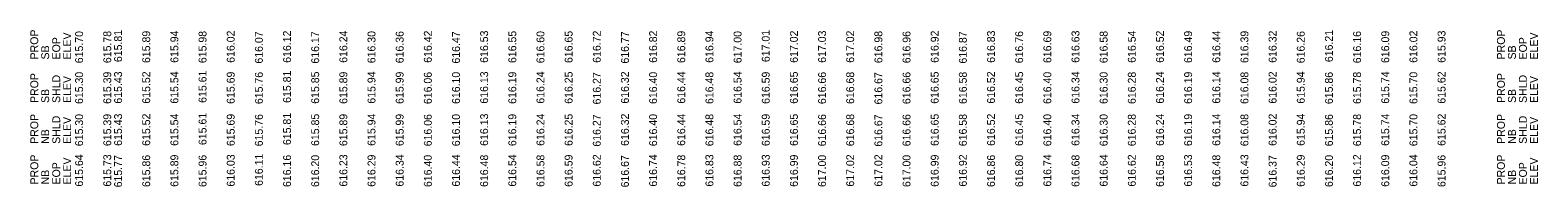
# Model space of a CAD drawing. Extents: x 19289 to 20627, y -348 to 1020.
# Drawn here: x 19289 to 20627, y -348 to -208 of the extents above; entities that cross this region are included whole.
import ezdxf

# ---------------------------------------------------------------- set-up
doc = ezdxf.new("R2010")
doc.units = 0
for name, color, linetype in [('PF_P_Text', 7, 'Continuous'), ('PF_P_Text_Strip_Grades_20', 7, 'Continuous'), ('PF_P_Text_Strip_Grades_LT', 7, 'Continuous'), ('PF_P_Text_Strip_Grades_RT', 7, 'Continuous')]:
    doc.layers.add(name, color=color, linetype=linetype)

msp = doc.modelspace()

# ---------------------------------------------------------------- texts
at = {"layer": 'PF_P_Text'}
for s, p in [('PROP ', (19295.9, -234.4)), ('ELEV', (19325.1, -234.4)), ('PROP ', (20598, -234.4)), ('ELEV', (20627.3, -234.4)), ('SB ', (19305.6, -234.4)), ('EOP', (19315.4, -234.4)), ('SB ', (20607.8, -234.4)), ('EOP', (20617.5, -234.4)), ('PROP ', (19295.9, -273.1)), ('SHLD ', (19315.4, -273.1)), ('ELEV', (19325.1, -273.1)), ('PROP ', (20598, -273.1)), ('SHLD', (20617.5, -273.1)), ('ELEV', (20627.3, -273.1)), ('SB ', (19305.6, -273.1)), ('SB ', (20607.8, -273.1)), ('PROP ', (19295.9, -309.4)), ('SHLD', (19315.4, -309.4)), ('ELEV', (19325.1, -309.4)), ('PROP ', (20598, -309.4)), ('SHLD', (20617.5, -309.4)), ('ELEV', (20627.3, -309.4)), ('NB ', (19305.6, -309.4)), ('NB ', (20607.8, -309.4)), ('PROP ', (19295.9, -345.5)), ('PROP ', (20598, -345.5)), ('NB ', (19305.6, -345.5)), ('EOP', (19315.4, -345.5)), ('ELEV', (19325.1, -345.5)), ('NB ', (20607.8, -345.5)), ('EOP', (20617.5, -345.5)), ('ELEV', (20627.3, -345.5))]:
    msp.add_text(s, height=7, rotation=90, dxfattribs=at).set_placement(p)
at = {"layer": 'PF_P_Text_Strip_Grades_20'}
for s, p in [('615.30', (19335.7, -274)), ('615.39', (19360.7, -273.9)), ('615.43', (19370.3, -273.7)), ('615.52', (19395.3, -273.7)), ('615.54', (19420.3, -273.7)), ('615.61', (19445.3, -273)), ('615.69', (19470.3, -273.9)), ('615.76', (19495.3, -274.1)), ('615.81', (19520.3, -273)), ('615.85', (19545.3, -273.8)), ('615.89', (19570.3, -273.9)), ('615.94', (19595.3, -273.7)), ('615.99', (19620.3, -273.9)), ('616.06', (19645.3, -274.1)), ('616.10', (19670.3, -274)), ('616.13', (19695.3, -273.7)), ('616.19', (19720.3, -273.9)), ('616.24', (19745.3, -273.7)), ('616.25', (19770.3, -273.8)), ('616.27', (19795.3, -274.4)), ('616.32', (19820.3, -273.7)), ('616.40', (19845.3, -274)), ('616.44', (19870.3, -273.7)), ('616.48', (19895.3, -274)), ('616.54', (19920.3, -273.7)), ('616.59', (19945.3, -273.9)), ('616.65', (19970.3, -273.8)), ('616.66', (19995.3, -274.1)), ('616.68', (20020.3, -274)), ('616.67', (20045.3, -274.4)), ('616.66', (20070.3, -274.1)), ('616.65', (20095.3, -273.8)), ('616.58', (20120.3, -274)), ('616.52', (20145.3, -273.7)), ('616.45', (20170.3, -273.8)), ('616.40', (20195.3, -274)), ('616.34', (20220.3, -273.7)), ('616.30', (20245.3, -274)), ('616.28', (20270.3, -274)), ('616.24', (20295.3, -273.7)), ('616.19', (20320.3, -273.9)), ('616.14', (20345.3, -273.7)), ('616.08', (20370.3, -274)), ('616.02', (20395.3, -273.7)), ('615.94', (20420.3, -273.7)), ('615.86', (20445.3, -274.1)), ('615.78', (20470.3, -274)), ('615.74', (20495.3, -273.7)), ('615.70', (20520.3, -274)), ('615.62', (20545.3, -273.7)), ('615.30', (19335.7, -311.5)), ('615.39', (19360.7, -311.4)), ('615.43', (19370.3, -311.2)), ('615.52', (19395.3, -311.2)), ('615.54', (19420.3, -311.2)), ('615.61', (19445.3, -310.5)), ('615.69', (19470.3, -311.4)), ('615.76', (19495.3, -311.6)), ('615.81', (19520.3, -310.5)), ('615.85', (19545.3, -311.3)), ('615.89', (19570.3, -311.4)), ('615.94', (19595.3, -311.2)), ('615.99', (19620.3, -311.4)), ('616.06', (19645.3, -311.6)), ('616.10', (19670.3, -311.5)), ('616.13', (19695.3, -311.2)), ('616.19', (19720.3, -311.4)), ('616.24', (19745.3, -311.2)), ('616.25', (19770.3, -311.3)), ('616.27', (19795.3, -311.9)), ('616.32', (19820.3, -311.2)), ('616.40', (19845.3, -311.5)), ('616.44', (19870.3, -311.2)), ('616.48', (19895.3, -311.5)), ('616.54', (19920.3, -311.2)), ('616.59', (19945.3, -311.4)), ('616.65', (19970.3, -311.3)), ('616.66', (19995.3, -311.6)), ('616.68', (20020.3, -311.5)), ('616.67', (20045.3, -311.9)), ('616.66', (20070.3, -311.6)), ('616.65', (20095.3, -311.3)), ('616.58', (20120.3, -311.5)), ('616.52', (20145.3, -311.2)), ('616.45', (20170.3, -311.3)), ('616.40', (20195.3, -311.5)), ('616.34', (20220.3, -311.2)), ('616.30', (20245.3, -311.5)), ('616.28', (20270.3, -311.5)), ('616.24', (20295.3, -311.2)), ('616.19', (20320.3, -311.4)), ('616.14', (20345.3, -311.2)), ('616.08', (20370.3, -311.5)), ('616.02', (20395.3, -311.2)), ('615.94', (20420.3, -311.2)), ('615.86', (20445.3, -311.6)), ('615.78', (20470.3, -311.5)), ('615.74', (20495.3, -311.2)), ('615.70', (20520.3, -311.5)), ('615.62', (20545.3, -311.2))]:
    msp.add_text(s, height=7, rotation=90, dxfattribs=at).set_placement(p)
at = {"layer": 'PF_P_Text_Strip_Grades_LT'}
for s, p in [('615.70', (19335.7, -237.8)), ('615.78', (19360.7, -237.7)), ('615.81', (19370.3, -236.8)), ('615.89', (19395.3, -237.6)), ('615.94', (19420.3, -237.4)), ('615.98', (19445.3, -237.7)), ('616.02', (19470.3, -237.4)), ('616.07', (19495.3, -238.1)), ('616.12', (19520.3, -237.4)), ('616.17', (19545.3, -238.1)), ('616.24', (19570.3, -237.4)), ('616.30', (19595.3, -237.8)), ('616.36', (19620.3, -237.8)), ('616.42', (19645.3, -237.4)), ('616.47', (19670.3, -238.1)), ('616.53', (19695.3, -237.4)), ('616.55', (19720.3, -237.6)), ('616.60', (19745.3, -237.8)), ('616.65', (19770.3, -237.6)), ('616.72', (19795.3, -237.4)), ('616.77', (19820.3, -238.1)), ('616.82', (19845.3, -237.4)), ('616.89', (19870.3, -237.6)), ('616.94', (19895.3, -237.4)), ('617.00', (19920.3, -237.8)), ('617.01', (19945.3, -236.8)), ('617.02', (19970.3, -237.4)), ('617.03', (19995.3, -237.4)), ('617.02', (20020.3, -237.4)), ('616.98', (20045.3, -237.7)), ('616.96', (20070.3, -237.8)), ('616.92', (20095.3, -237.4)), ('616.87', (20120.3, -238.1)), ('616.83', (20145.3, -237.4)), ('616.76', (20170.3, -237.8)), ('616.69', (20195.3, -237.6)), ('616.63', (20220.3, -237.4)), ('616.58', (20245.3, -237.7)), ('616.54', (20270.3, -237.4)), ('616.52', (20295.3, -237.4)), ('616.49', (20320.3, -237.6)), ('616.44', (20345.3, -237.4)), ('616.39', (20370.3, -237.6)), ('616.32', (20395.3, -237.4)), ('616.26', (20420.3, -237.8)), ('616.21', (20445.3, -236.8)), ('616.16', (20470.3, -237.8)), ('616.09', (20495.3, -237.6)), ('616.02', (20520.3, -237.4)), ('615.93', (20545.3, -237.4))]:
    msp.add_text(s, height=7, rotation=90, dxfattribs=at).set_placement(p)
at = {"layer": 'PF_P_Text_Strip_Grades_RT'}
for s, p in [('615.64', (19335.7, -347.4)), ('615.73', (19360.7, -347.4)), ('615.77', (19370.3, -348.1)), ('615.86', (19395.3, -347.8)), ('615.89', (19420.3, -347.6)), ('615.96', (19445.3, -347.8)), ('616.03', (19470.3, -347.4)), ('616.11', (19495.3, -346.8)), ('616.16', (19520.3, -347.8)), ('616.20', (19545.3, -347.8)), ('616.23', (19570.3, -347.4)), ('616.29', (19595.3, -347.6)), ('616.34', (19620.3, -347.4)), ('616.40', (19645.3, -347.8)), ('616.44', (19670.3, -347.4)), ('616.48', (19695.3, -347.7)), ('616.54', (19720.3, -347.4)), ('616.58', (19745.3, -347.7)), ('616.59', (19770.3, -347.6)), ('616.62', (19795.3, -347.4)), ('616.67', (19820.3, -348.1)), ('616.74', (19845.3, -347.4)), ('616.78', (19870.3, -347.7)), ('616.83', (19895.3, -347.4)), ('616.88', (19920.3, -347.7)), ('616.93', (19945.3, -347.4)), ('616.99', (19970.3, -347.6)), ('617.00', (19995.3, -347.8)), ('617.02', (20020.3, -347.4)), ('617.02', (20045.3, -347.4)), ('617.00', (20070.3, -347.8)), ('616.99', (20095.3, -347.6)), ('616.92', (20120.3, -347.4)), ('616.86', (20145.3, -347.8)), ('616.80', (20170.3, -347.8)), ('616.74', (20195.3, -347.4)), ('616.68', (20220.3, -347.7)), ('616.64', (20245.3, -347.4)), ('616.62', (20270.3, -347.4)), ('616.58', (20295.3, -347.7)), ('616.53', (20320.3, -347.4)), ('616.48', (20345.3, -347.7)), ('616.43', (20370.3, -347.4)), ('616.37', (20395.3, -348.1)), ('616.29', (20420.3, -347.6)), ('616.20', (20445.3, -347.8)), ('616.12', (20470.3, -347.4)), ('616.09', (20495.3, -347.6)), ('616.04', (20520.3, -347.4)), ('615.96', (20545.3, -347.8))]:
    msp.add_text(s, height=7, rotation=90, dxfattribs=at).set_placement(p)

doc.saveas('drawing.dxf')
